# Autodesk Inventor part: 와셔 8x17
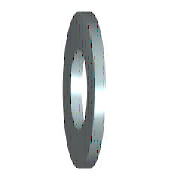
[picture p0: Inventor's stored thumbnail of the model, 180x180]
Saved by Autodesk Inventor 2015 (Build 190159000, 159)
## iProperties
Created: 2012-02
Part Number: 와셔 8x17
Material: 강철, 연강
Description: 평면 와셔
Document SubType Name: Modeling
Standard: KS B 1326
Designer: mduedu
Standards Organization: KS
Language: ko-KR
Size Designation: 8x17
Categories: <MemberInstance><Categories><Category DisplayName="조임쇠" InternalName="e4da775c-781d-43d5-af7c-5136215cf5a6" Mnemonic="FSTN"><Category DisplayName="와셔" InternalN
Density: 7.85 g/cm^3
Appearance: 파란색 - 벽 페인트 - 광택
Mass: 2.05184 g
Surface Area: 4.57416 cm^2
Volume: 0.261381 cm^3
IsCustomPart: 1
Author: mduedu
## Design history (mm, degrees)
sketch "스케치"
  geometry: C1 r 8.5 at (0, 0); C2 r 4.5 at (0, 0); 1 further point
  constraints: 2 centre point, 2 coincident
  dimensions: "d0" = 9 diameter of C2 (= SD1); "d1" = 17 diameter of C1 (= SD2)
extrude "본체" new body sketch "스케치" distance "d2" = 1.6 (= SD); taper "d3" = 0 deg
workaxis "Work Axis1"
workplane "Work Plane1"
body "Solid1"
other parameters: "SD1" = 9 [user parameter; used in 1 equation term], "SD2" = 17 [user parameter; used in 1 equation term], "SD" = 1.6 [user parameter; used in 1 equation term], "d4" = 0, "d5" = 0, "d6" = 0, "d7" = 0, "NND" = 8 [user parameter]
